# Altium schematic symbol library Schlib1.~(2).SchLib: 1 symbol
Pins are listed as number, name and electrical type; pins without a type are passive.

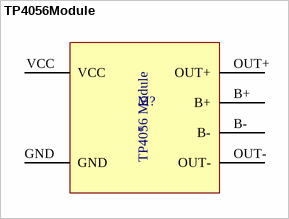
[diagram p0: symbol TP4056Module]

## TP4056Module
designator M?
TP4056 Module for managing battery charging
pins: B+, B-, GND, OUT+, OUT-, VCC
